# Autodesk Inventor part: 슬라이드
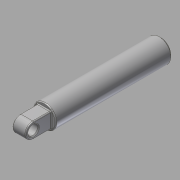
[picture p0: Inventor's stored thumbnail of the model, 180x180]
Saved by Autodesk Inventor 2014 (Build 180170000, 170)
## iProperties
Created: 2016-02
Part Number: 슬라이드
Material: 강철, 연강
Document SubType Name: Modeling
Designer: test
Density: 7.86 g/cm^3
Appearance: 강철
Mass: 54.6777 g
Surface Area: 30.7942 cm^2
Volume: 6.95645 cm^3
Author: test
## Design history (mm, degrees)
sketch "스케치2"
  geometry: C1 r 6 at (0, 0); 1 further point
  constraints: 1 centre point, 1 coincident
  dimensions: "d0" = 12 diameter of C1
extrude "돌출1" new body sketch "스케치2" distance "d1" = 60; taper "d2" = 0 deg
hole "구멍1" diameter "d5" = 5.917; stored, may be unused: countersink angle "d9" = 90 deg, drill point angle "d11" = 118 deg; dims "d3" = 10, "d4" = 10, "d6" = 10, "d7" = 4, "d8" = 2, "d10" = 12
chamfer "모따기1" distance "d12" = 1; stored, may be unused: second distance "d13" = 2, angle "d14" = 45 deg
sketch "스케치3"
  geometry: L1 (0, 6)-(0, -6) reference; L2 (0, 4)-(-9, 4); L3 (-9, -4)-(0, -4); L4 (0, -4)-(0, 4); C1 r 2.5 at (-9, 0); A1 r 4 centre (-9, 0) between (-9, 4) and (-9, -4); 2 further points
  constraints: 6 end point, 2 centre point, 2 point on circle, 2 tangent, 1 coincident, 1 horizontal, 1 horizontal alignment, 1 midpoint, 1 parallel, 1 point on line, 1 vertical
  dimensions: "d15" = 13 dimension on A1 L1; "d16" = 8 distance between parallel lines of L3 L2; "d17" = 5 diameter of C1
extrude "돌출2" join sketch "스케치3" stored distance "d18" = 7; taper "d19" = 0 deg
chamfer "모따기2" distance "d20" = 0.5; stored, may be unused: second distance "d21" = 2, angle "d22" = 45 deg
fillet "모깎기1" dims "d23" = 0.5
fillet "모깎기2" dims "d24" = 0.5
fillet "모깎기3" dims "d25" = 0.5
node "솔리드1"
